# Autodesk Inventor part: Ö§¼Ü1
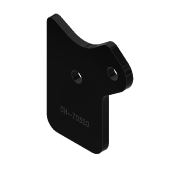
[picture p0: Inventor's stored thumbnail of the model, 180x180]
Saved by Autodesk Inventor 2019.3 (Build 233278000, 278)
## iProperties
Created: 2017-10
Part Number: Ö§¼Ü1
Material: Ogólny
Document SubType Name: Modeling
Designer: CADENGINEERING4
Density: 1 g/cm^3
Appearance: Gładki — czarny
Author: CADENGINEERING4
Revision Number: ÈÎºÎ
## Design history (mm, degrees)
feature "°ü¸²1"
node "Bryła1"
